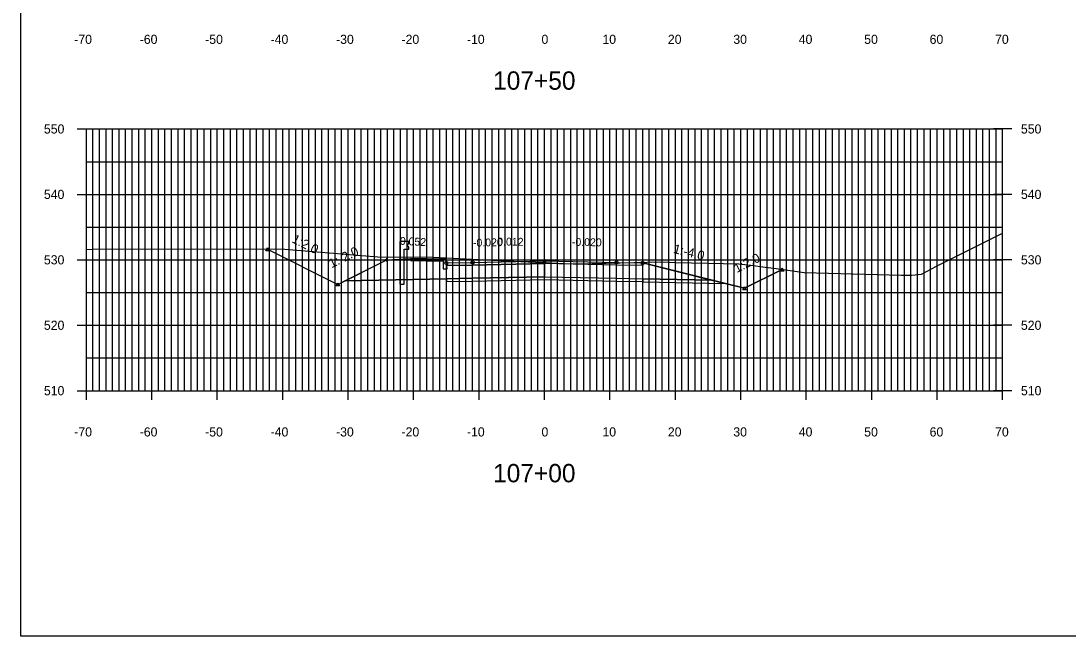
# Model space of a CAD drawing. Extents: x 1509063 to 1512863, y 401160 to 402918.
# Drawn here: x 1512182.7 to 1512342.7, y 402252.1 to 402346.1 of the extents above; entities that cross this region are included whole.
import ezdxf

# ---------------------------------------------------------------- set-up
doc = ezdxf.new("R2010")
doc.units = 0
for name, color, linetype in [('DD_P', 7, 'Continuous'), ('LCUT_P', 7, 'Continuous'), ('NBL1', 7, 'Continuous'), ('PET_P', 7, 'Continuous'), ('PRC', 7, 'Continuous'), ('PSP_P', 7, 'Continuous'), ('RBS_P', 7, 'Continuous'), ('RCC_P', 7, 'Continuous'), ('RGR_P', 7, 'Continuous'), ('XAX_P', 7, 'Continuous'), ('XAXTIC_P', 7, 'Continuous'), ('XAXTXT_P_T', 7, 'Continuous'), ('XGL_P', 7, 'Continuous'), ('XSL1_P', 7, 'Continuous'), ('XSL1_P_T', 7, 'Continuous'), ('XSL2_P', 7, 'Continuous'), ('XSL3_P', 7, 'Continuous'), ('XSLOG', 7, 'Continuous')]:
    doc.layers.add(name, color=color, linetype=linetype)

msp = doc.modelspace()

# ---------------------------------------------------------------- linework, layer by layer
at = {"layer": 'DD_P'}
for points in [[(1512220.38, 402311.2), (1512231.13, 402305.83), (1512238.65, 402309.59), (1512242.23, 402309.8)], [(1512290.41, 402305.94), (1512277.73, 402309.11)], [(1512299.06, 402308.12), (1512293.27, 402305.23), (1512290.41, 402305.94)]]:
    msp.add_lwpolyline(points, dxfattribs=at)
for points in [[(1512231.13, 402306.08), (1512231.38, 402305.58), (1512230.88, 402305.58)], [(1512293.27, 402305.48), (1512293.52, 402304.98), (1512293.02, 402304.98)]]:
    msp.add_lwpolyline(points, close=True, dxfattribs=at)
at = {"layer": 'LCUT_P'}
for points in [[(1512220.38, 402311.45), (1512220.63, 402310.95), (1512220.13, 402310.95)], [(1512299.06, 402308.37), (1512299.31, 402307.87), (1512298.81, 402307.87)]]:
    msp.add_lwpolyline(points, close=True, dxfattribs=at)
at = {"layer": 'NBL1'}
msp.add_lwpolyline([(1512502.73, 402252.08), (1512182.73, 402252.08), (1512182.73, 402462.08), (1512502.73, 402462.08)], close=True, dxfattribs=at)
at = {"layer": 'PET_P'}
for centre in [(1512251.73, 402309.19), (1512273.73, 402309.19)]:
    msp.add_circle(centre, 0.25, dxfattribs=at)
at = {"layer": 'PRC'}
msp.add_circle((1512262.73, 402309.41), 0.25, dxfattribs=at)
at = {"layer": 'PSP_P'}
for centre in [(1512247.73, 402309.11), (1512277.73, 402309.11)]:
    msp.add_circle(centre, 0.25, dxfattribs=at)
at = {"layer": 'RBS_P'}
for points in [[(1512247.8, 402308.7), (1512251.73, 402308.78), (1512262.72, 402309), (1512262.72, 402307), (1512251.73, 402306.78), (1512247.8, 402306.7), (1512232.24, 402306.39), (1512238.65, 402309.59), (1512242.23, 402309.8), (1512242.23, 402309.47), (1512247.23, 402309.37), (1512247.23, 402308.2), (1512247.88, 402308.2)], [(1512262.72, 402309), (1512262.72, 402307), (1512273.73, 402306.78), (1512277.73, 402306.7), (1512288.24, 402306.49), (1512277.73, 402309.11), (1512277.73, 402308.7), (1512273.73, 402308.78)]]:
    msp.add_lwpolyline(points, close=True, dxfattribs=at)
for points in [[(1512238.65, 402309.59), (1512238.65, 402309.84), (1512238.65, 402309.59), (1512238.4, 402309.59), (1512238.65, 402309.59), (1512238.65, 402309.34), (1512238.65, 402309.59), (1512238.9, 402309.59)], [(1512277.73, 402309.11), (1512277.73, 402309.36), (1512277.73, 402309.11), (1512277.48, 402309.11), (1512277.73, 402309.11), (1512277.73, 402308.86), (1512277.73, 402309.11), (1512277.98, 402309.11)]]:
    msp.add_lwpolyline(points, dxfattribs=at)
at = {"layer": 'RCC_P'}
msp.add_lwpolyline([(1512247.73, 402309.11), (1512247.63, 402309.7), (1512247.23, 402309.7), (1512247.23, 402308.2), (1512247.88, 402308.2)], close=True, dxfattribs=at)
at = {"layer": 'RGR_P'}
msp.add_lwpolyline([(1512241.29, 402311.2), (1512241.98, 402311.2), (1512241.98, 402311.5), (1512241.68, 402311.79), (1512241.98, 402312.08), (1512241.98, 402312.38), (1512240.6, 402312.38), (1512240.6, 402305.88), (1512241.29, 402305.88)], close=True, dxfattribs=at)
at = {"layer": 'XAX_P'}
for p, q in [((1512192.73, 402289.58), (1512192.73, 402329.58)), ((1512262.73, 402289.58), (1512262.73, 402329.58)), ((1512332.73, 402289.58), (1512332.73, 402329.58)), ((1512192.73, 402289.58), (1512332.73, 402289.58))]:
    msp.add_line(p, q, dxfattribs=at)
at = {"layer": 'XAXTIC_P'}
for p, q in [((1512191.33, 402329.58), (1512194.13, 402329.58)), ((1512261.33, 402329.58), (1512264.13, 402329.58)), ((1512334.13, 402329.58), (1512331.33, 402329.58)), ((1512191.33, 402319.58), (1512194.13, 402319.58)), ((1512261.33, 402319.58), (1512264.13, 402319.58)), ((1512334.13, 402319.58), (1512331.33, 402319.58)), ((1512191.33, 402309.58), (1512194.13, 402309.58)), ((1512261.33, 402309.58), (1512264.13, 402309.58)), ((1512334.13, 402309.58), (1512331.33, 402309.58)), ((1512191.33, 402299.58), (1512194.13, 402299.58)), ((1512261.33, 402299.58), (1512264.13, 402299.58)), ((1512334.13, 402299.58), (1512331.33, 402299.58)), ((1512192.73, 402288.18), (1512192.73, 402290.98)), ((1512202.73, 402288.18), (1512202.73, 402290.98)), ((1512212.73, 402288.18), (1512212.73, 402290.98)), ((1512222.73, 402288.18), (1512222.73, 402290.98)), ((1512232.73, 402288.18), (1512232.73, 402290.98)), ((1512242.73, 402288.18), (1512242.73, 402290.98)), ((1512252.73, 402288.18), (1512252.73, 402290.98)), ((1512262.73, 402288.18), (1512262.73, 402290.98)), ((1512272.73, 402288.18), (1512272.73, 402290.98)), ((1512282.73, 402288.18), (1512282.73, 402290.98)), ((1512292.73, 402288.18), (1512292.73, 402290.98)), ((1512302.73, 402288.18), (1512302.73, 402290.98)), ((1512312.73, 402288.18), (1512312.73, 402290.98)), ((1512322.73, 402288.18), (1512322.73, 402290.98)), ((1512332.73, 402288.18), (1512332.73, 402290.98)), ((1512191.33, 402289.58), (1512194.13, 402289.58)), ((1512261.33, 402289.58), (1512264.13, 402289.58)), ((1512334.13, 402289.58), (1512331.33, 402289.58))]:
    msp.add_line(p, q, dxfattribs=at)
at = {"layer": 'XGL_P'}
for p, q in [((1512192.73, 402329.58), (1512332.73, 402329.58)), ((1512192.73, 402289.58), (1512192.73, 402329.58)), ((1512193.73, 402289.58), (1512193.73, 402329.58)), ((1512194.73, 402289.58), (1512194.73, 402329.58)), ((1512195.73, 402289.58), (1512195.73, 402329.58)), ((1512196.73, 402289.58), (1512196.73, 402329.58)), ((1512197.73, 402289.58), (1512197.73, 402329.58)), ((1512198.73, 402289.58), (1512198.73, 402329.58)), ((1512199.73, 402289.58), (1512199.73, 402329.58)), ((1512200.73, 402289.58), (1512200.73, 402329.58)), ((1512201.73, 402289.58), (1512201.73, 402329.58)), ((1512202.73, 402289.58), (1512202.73, 402329.58)), ((1512203.73, 402289.58), (1512203.73, 402329.58)), ((1512204.73, 402289.58), (1512204.73, 402329.58)), ((1512205.73, 402289.58), (1512205.73, 402329.58)), ((1512206.73, 402289.58), (1512206.73, 402329.58)), ((1512207.73, 402289.58), (1512207.73, 402329.58)), ((1512208.73, 402289.58), (1512208.73, 402329.58)), ((1512209.73, 402289.58), (1512209.73, 402329.58)), ((1512210.73, 402289.58), (1512210.73, 402329.58)), ((1512211.73, 402289.58), (1512211.73, 402329.58)), ((1512212.73, 402289.58), (1512212.73, 402329.58)), ((1512213.73, 402289.58), (1512213.73, 402329.58)), ((1512214.73, 402289.58), (1512214.73, 402329.58)), ((1512215.73, 402289.58), (1512215.73, 402329.58)), ((1512216.73, 402289.58), (1512216.73, 402329.58)), ((1512217.73, 402289.58), (1512217.73, 402329.58)), ((1512218.73, 402289.58), (1512218.73, 402329.58)), ((1512219.73, 402289.58), (1512219.73, 402329.58)), ((1512220.73, 402289.58), (1512220.73, 402329.58)), ((1512221.73, 402289.58), (1512221.73, 402329.58)), ((1512222.73, 402289.58), (1512222.73, 402329.58)), ((1512223.73, 402289.58), (1512223.73, 402329.58)), ((1512224.73, 402289.58), (1512224.73, 402329.58)), ((1512225.73, 402289.58), (1512225.73, 402329.58)), ((1512226.73, 402289.58), (1512226.73, 402329.58)), ((1512227.73, 402289.58), (1512227.73, 402329.58)), ((1512228.73, 402289.58), (1512228.73, 402329.58)), ((1512229.73, 402289.58), (1512229.73, 402329.58)), ((1512230.73, 402289.58), (1512230.73, 402329.58)), ((1512231.73, 402289.58), (1512231.73, 402329.58)), ((1512232.73, 402289.58), (1512232.73, 402329.58)), ((1512233.73, 402289.58), (1512233.73, 402329.58)), ((1512234.73, 402289.58), (1512234.73, 402329.58)), ((1512235.73, 402289.58), (1512235.73, 402329.58)), ((1512236.73, 402289.58), (1512236.73, 402329.58)), ((1512237.73, 402289.58), (1512237.73, 402329.58)), ((1512238.73, 402289.58), (1512238.73, 402329.58)), ((1512239.73, 402289.58), (1512239.73, 402329.58)), ((1512240.73, 402289.58), (1512240.73, 402329.58)), ((1512241.73, 402289.58), (1512241.73, 402329.58)), ((1512242.73, 402289.58), (1512242.73, 402329.58)), ((1512243.73, 402289.58), (1512243.73, 402329.58)), ((1512244.73, 402289.58), (1512244.73, 402329.58)), ((1512245.73, 402289.58), (1512245.73, 402329.58)), ((1512246.73, 402289.58), (1512246.73, 402329.58)), ((1512247.73, 402289.58), (1512247.73, 402329.58)), ((1512248.73, 402289.58), (1512248.73, 402329.58)), ((1512249.73, 402289.58), (1512249.73, 402329.58)), ((1512250.73, 402289.58), (1512250.73, 402329.58)), ((1512251.73, 402289.58), (1512251.73, 402329.58)), ((1512252.73, 402289.58), (1512252.73, 402329.58)), ((1512253.73, 402289.58), (1512253.73, 402329.58)), ((1512254.73, 402289.58), (1512254.73, 402329.58)), ((1512255.73, 402289.58), (1512255.73, 402329.58)), ((1512256.73, 402289.58), (1512256.73, 402329.58)), ((1512257.73, 402289.58), (1512257.73, 402329.58)), ((1512258.73, 402289.58), (1512258.73, 402329.58)), ((1512259.73, 402289.58), (1512259.73, 402329.58)), ((1512260.73, 402289.58), (1512260.73, 402329.58)), ((1512261.73, 402289.58), (1512261.73, 402329.58)), ((1512262.73, 402289.58), (1512262.73, 402329.58)), ((1512263.73, 402289.58), (1512263.73, 402329.58)), ((1512264.73, 402289.58), (1512264.73, 402329.58)), ((1512265.73, 402289.58), (1512265.73, 402329.58)), ((1512266.73, 402289.58), (1512266.73, 402329.58)), ((1512267.73, 402289.58), (1512267.73, 402329.58)), ((1512268.73, 402289.58), (1512268.73, 402329.58)), ((1512269.73, 402289.58), (1512269.73, 402329.58)), ((1512270.73, 402289.58), (1512270.73, 402329.58)), ((1512271.73, 402289.58), (1512271.73, 402329.58)), ((1512272.73, 402289.58), (1512272.73, 402329.58)), ((1512273.73, 402289.58), (1512273.73, 402329.58)), ((1512274.73, 402289.58), (1512274.73, 402329.58)), ((1512275.73, 402289.58), (1512275.73, 402329.58)), ((1512276.73, 402289.58), (1512276.73, 402329.58)), ((1512277.73, 402289.58), (1512277.73, 402329.58)), ((1512278.73, 402289.58), (1512278.73, 402329.58)), ((1512279.73, 402289.58), (1512279.73, 402329.58)), ((1512280.73, 402289.58), (1512280.73, 402329.58)), ((1512281.73, 402289.58), (1512281.73, 402329.58)), ((1512282.73, 402289.58), (1512282.73, 402329.58)), ((1512283.73, 402289.58), (1512283.73, 402329.58)), ((1512284.73, 402289.58), (1512284.73, 402329.58)), ((1512285.73, 402289.58), (1512285.73, 402329.58)), ((1512286.73, 402289.58), (1512286.73, 402329.58)), ((1512287.73, 402289.58), (1512287.73, 402329.58)), ((1512288.73, 402289.58), (1512288.73, 402329.58)), ((1512289.73, 402289.58), (1512289.73, 402329.58)), ((1512290.73, 402289.58), (1512290.73, 402329.58)), ((1512291.73, 402289.58), (1512291.73, 402329.58)), ((1512292.73, 402289.58), (1512292.73, 402329.58)), ((1512293.73, 402289.58), (1512293.73, 402329.58)), ((1512294.73, 402289.58), (1512294.73, 402329.58)), ((1512295.73, 402289.58), (1512295.73, 402329.58)), ((1512296.73, 402289.58), (1512296.73, 402329.58)), ((1512297.73, 402289.58), (1512297.73, 402329.58)), ((1512298.73, 402289.58), (1512298.73, 402329.58)), ((1512299.73, 402289.58), (1512299.73, 402329.58)), ((1512300.73, 402289.58), (1512300.73, 402329.58)), ((1512301.73, 402289.58), (1512301.73, 402329.58)), ((1512302.73, 402289.58), (1512302.73, 402329.58)), ((1512303.73, 402289.58), (1512303.73, 402329.58)), ((1512304.73, 402289.58), (1512304.73, 402329.58)), ((1512305.73, 402289.58), (1512305.73, 402329.58)), ((1512306.73, 402289.58), (1512306.73, 402329.58)), ((1512307.73, 402289.58), (1512307.73, 402329.58)), ((1512308.73, 402289.58), (1512308.73, 402329.58)), ((1512309.73, 402289.58), (1512309.73, 402329.58)), ((1512310.73, 402289.58), (1512310.73, 402329.58)), ((1512311.73, 402289.58), (1512311.73, 402329.58)), ((1512312.73, 402289.58), (1512312.73, 402329.58)), ((1512313.73, 402289.58), (1512313.73, 402329.58)), ((1512314.73, 402289.58), (1512314.73, 402329.58)), ((1512315.73, 402289.58), (1512315.73, 402329.58)), ((1512316.73, 402289.58), (1512316.73, 402329.58)), ((1512317.73, 402289.58), (1512317.73, 402329.58)), ((1512318.73, 402289.58), (1512318.73, 402329.58)), ((1512319.73, 402289.58), (1512319.73, 402329.58)), ((1512320.73, 402289.58), (1512320.73, 402329.58)), ((1512321.73, 402289.58), (1512321.73, 402329.58)), ((1512322.73, 402289.58), (1512322.73, 402329.58)), ((1512323.73, 402289.58), (1512323.73, 402329.58)), ((1512324.73, 402289.58), (1512324.73, 402329.58)), ((1512325.73, 402289.58), (1512325.73, 402329.58)), ((1512326.73, 402289.58), (1512326.73, 402329.58)), ((1512327.73, 402289.58), (1512327.73, 402329.58)), ((1512328.73, 402289.58), (1512328.73, 402329.58)), ((1512329.73, 402289.58), (1512329.73, 402329.58)), ((1512330.73, 402289.58), (1512330.73, 402329.58)), ((1512331.73, 402289.58), (1512331.73, 402329.58)), ((1512332.73, 402289.58), (1512332.73, 402329.58)), ((1512192.73, 402324.58), (1512332.73, 402324.58)), ((1512192.73, 402319.58), (1512332.73, 402319.58)), ((1512192.73, 402314.58), (1512332.73, 402314.58)), ((1512192.73, 402309.58), (1512332.73, 402309.58)), ((1512192.73, 402304.58), (1512332.73, 402304.58)), ((1512192.73, 402299.58), (1512332.73, 402299.58)), ((1512192.73, 402294.58), (1512332.73, 402294.58)), ((1512192.73, 402289.58), (1512332.73, 402289.58))]:
    msp.add_line(p, q, dxfattribs=at)
at = {"layer": 'XSL1_P'}
msp.add_lwpolyline([(1512220.38, 402311.2), (1512231.13, 402305.83), (1512232.24, 402306.39), (1512238.65, 402309.59), (1512242.23, 402309.8), (1512247.23, 402309.7), (1512247.63, 402309.7), (1512247.73, 402309.11), (1512251.73, 402309.19), (1512262.73, 402309.41), (1512273.73, 402309.19), (1512277.73, 402309.11), (1512288.24, 402306.49), (1512290.41, 402305.94), (1512293.27, 402305.23), (1512299.06, 402308.12)], dxfattribs=at)
msp.add_lwpolyline([(1512247.23, 402309.7), (1512242.23, 402309.8), (1512242.23, 402309.47), (1512247.23, 402309.37)], close=True, dxfattribs=at)
at = {"layer": 'XSL2_P'}
for points in [[(1512232.24, 402306.39), (1512247.8, 402306.7)], [(1512288.24, 402306.49), (1512277.73, 402306.7)]]:
    msp.add_lwpolyline(points, dxfattribs=at)
for points in [[(1512273.73, 402306.28), (1512262.72, 402306.5), (1512251.73, 402306.28), (1512247.8, 402306.2), (1512247.8, 402306.7), (1512251.73, 402306.78), (1512262.72, 402307), (1512273.73, 402306.78), (1512277.73, 402306.7), (1512277.73, 402306.2)], [(1512277.73, 402306.7), (1512277.73, 402306.2), (1512290.41, 402305.94), (1512288.24, 402306.49)]]:
    msp.add_lwpolyline(points, close=True, dxfattribs=at)
at = {"layer": 'XSL3_P'}
msp.add_lwpolyline([(1512251.73, 402308.78), (1512247.8, 402308.7), (1512247.73, 402309.11), (1512251.73, 402309.19), (1512262.72, 402309.41), (1512273.73, 402309.19), (1512277.73, 402309.11), (1512277.73, 402308.7), (1512273.73, 402308.78), (1512262.72, 402309)], close=True, dxfattribs=at)
at = {"layer": 'XSLOG'}
msp.add_lwpolyline([(1512192.73, 402311.14), (1512194.77, 402311.24), (1512223.04, 402311.2), (1512237.26, 402310.04), (1512245.78, 402309.97), (1512255.8, 402309.5), (1512265.81, 402309.04), (1512267.87, 402308.99), (1512276.42, 402309.17), (1512280.4, 402309.25), (1512282.82, 402309.19), (1512292.4, 402308.96), (1512294.25, 402308.74), (1512296.44, 402308.48), (1512297.78, 402308.32), (1512302.4, 402307.62), (1512317.3, 402307.24), (1512317.66, 402307.23), (1512318.86, 402307.21), (1512320.34, 402307.39), (1512322.61, 402308.6), (1512332.73, 402313.63)], dxfattribs=at)

# ---------------------------------------------------------------- texts
at = {"layer": 'XAXTXT_P_T'}
for s, height, p in [('-70', 1.4, (1512190.88, 402342.58)), ('-60', 1.4, (1512200.88, 402342.58)), ('-50', 1.4, (1512210.88, 402342.58)), ('-40', 1.4, (1512220.88, 402342.58)), ('-30', 1.4, (1512230.88, 402342.58)), ('-20', 1.4, (1512240.88, 402342.58)), ('-10', 1.4, (1512250.88, 402342.58)), ('0', 1.4, (1512262.27, 402342.58)), ('10', 1.4, (1512271.58, 402342.58)), ('20', 1.4, (1512281.58, 402342.58)), ('30', 1.4, (1512291.58, 402342.58)), ('40', 1.4, (1512301.58, 402342.58)), ('50', 1.4, (1512311.58, 402342.58)), ('60', 1.4, (1512321.58, 402342.58)), ('70', 1.4, (1512331.58, 402342.58)), ('107+50', 2.8, (1512254.87, 402335.58)), ('550', 1.4, (1512186.24, 402328.88)), ('550', 1.4, (1512335.53, 402328.88)), ('540', 1.4, (1512186.24, 402318.88)), ('540', 1.4, (1512335.53, 402318.88)), ('530', 1.4, (1512186.24, 402308.88)), ('530', 1.4, (1512335.53, 402308.88)), ('520', 1.4, (1512186.24, 402298.88)), ('520', 1.4, (1512335.53, 402298.88)), ('510', 1.4, (1512186.24, 402288.88)), ('510', 1.4, (1512335.53, 402288.88)), ('-70', 1.4, (1512190.88, 402282.58)), ('-60', 1.4, (1512200.88, 402282.58)), ('-50', 1.4, (1512210.88, 402282.58)), ('-40', 1.4, (1512220.88, 402282.58)), ('-30', 1.4, (1512230.88, 402282.58)), ('-20', 1.4, (1512240.88, 402282.58)), ('-10', 1.4, (1512250.88, 402282.58)), ('0', 1.4, (1512262.27, 402282.58)), ('10', 1.4, (1512271.58, 402282.58)), ('20', 1.4, (1512281.58, 402282.58)), ('30', 1.4, (1512291.58, 402282.58)), ('40', 1.4, (1512301.58, 402282.58)), ('50', 1.4, (1512311.58, 402282.58)), ('60', 1.4, (1512321.58, 402282.58)), ('70', 1.4, (1512331.58, 402282.58)), ('107+00', 2.8, (1512254.87, 402275.58))]:
    msp.add_text(s, height=height, dxfattribs=at).set_placement(p)
at = {"layer": 'XSL1_P_T'}
for s, height, rotation, p in [('1:2.0', 1.4, 333.4349, (1512224.02, 402312.29)), ('1:2.0', 1.4, 333.4349, (1512224.02, 402312.29)), ('1:2.0', 1.4, 333.4349, (1512224.02, 402312.29)), ('0.052', 1.2, 356.9978, (1512240.6, 402311.89)), ('-0.020', 1.2, 1.1458, (1512251.81, 402311.59)), ('0.012', 1.2, 359.3017, (1512255.5, 402311.78)), ('0.012', 1.2, 359.3017, (1512255.5, 402311.78)), ('-0.020', 1.2, 358.8542, (1512266.91, 402311.73)), ('1:-2.0', 1.4, 26.5651, (1512230.21, 402308.28)), ('1:-2.0', 1.4, 26.5651, (1512230.21, 402308.28)), ('1:-2.0', 1.4, 26.5651, (1512230.21, 402308.28)), ('1:-4.0', 1.4, 345.9638, (1512282.32, 402310.65)), ('1:-4.0', 1.4, 345.9638, (1512282.32, 402310.65)), ('1:-4.0', 1.4, 345.9638, (1512282.32, 402310.65)), ('1:2.0', 1.4, 26.5651, (1512292.11, 402307.55)), ('1:2.0', 1.4, 26.5651, (1512292.11, 402307.55)), ('1:2.0', 1.4, 26.5651, (1512292.11, 402307.55))]:
    msp.add_text(s, height=height, rotation=rotation, dxfattribs=at).set_placement(p)

doc.saveas('drawing.dxf')
